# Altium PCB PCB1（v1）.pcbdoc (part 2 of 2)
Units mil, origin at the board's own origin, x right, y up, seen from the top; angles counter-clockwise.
Board outline 4301.67 x 3812.23 mil, 2 copper layers (Top Layer, Bottom Layer); 110 components, 92 nets, 368 pads, 77 vias.
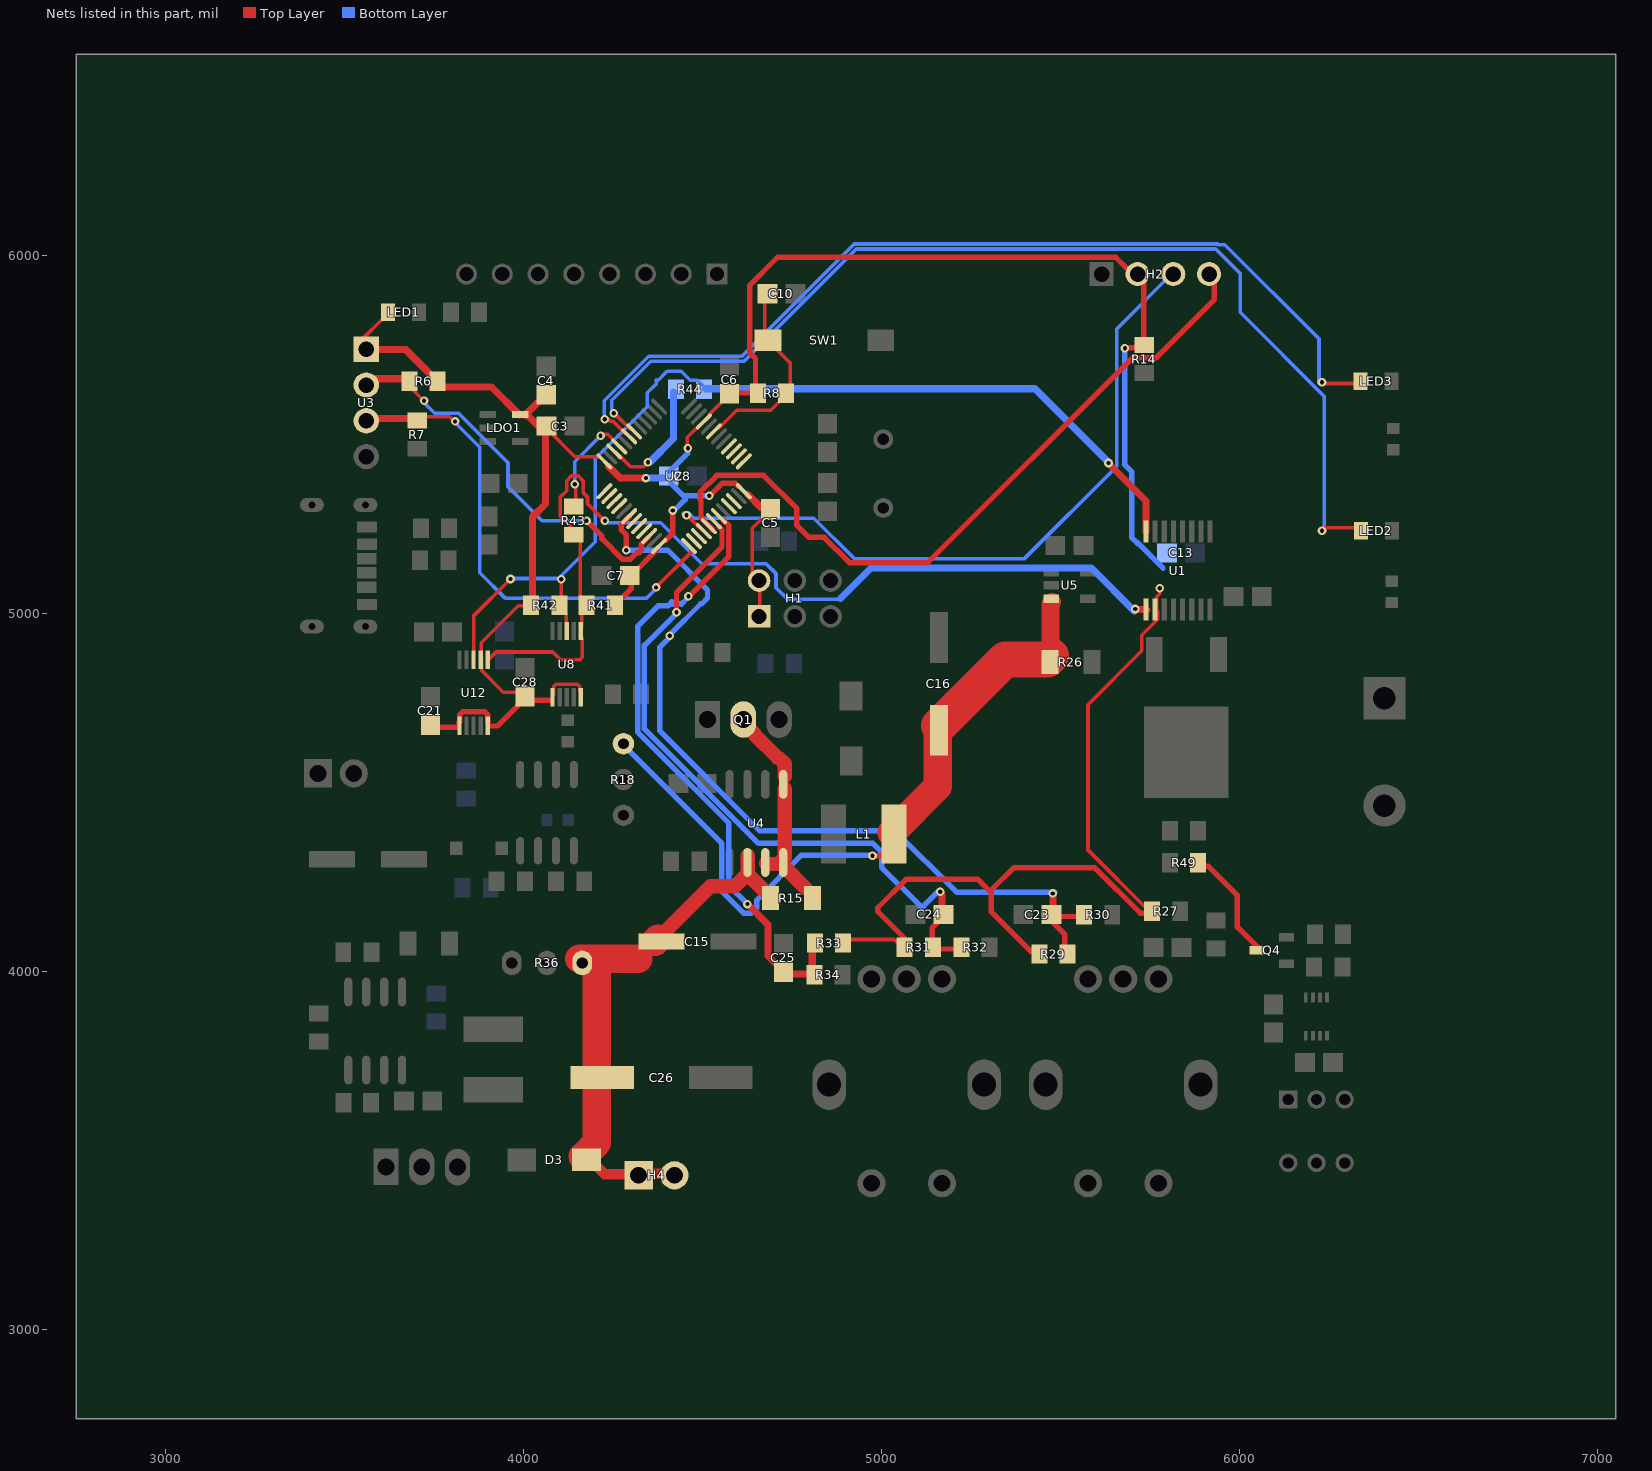
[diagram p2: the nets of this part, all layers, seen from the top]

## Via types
v1: diameter 24.02, hole 12.01, Top Layer to Bottom Layer, 77 vias

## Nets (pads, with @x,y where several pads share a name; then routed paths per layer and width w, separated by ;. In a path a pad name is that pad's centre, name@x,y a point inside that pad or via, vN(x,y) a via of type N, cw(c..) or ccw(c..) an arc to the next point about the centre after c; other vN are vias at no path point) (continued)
PA9: C23.2 R29.2 R30.1 U2.30 | length 2386.2
  Top Layer w15: v1(4287.02,5176.42) 4287.02,5218.92 4273.09,5232.85 4273.09,5248.42 U2.30@4295.09,5270.42 ; C23.2@5466.9,4149.18 5511.87,4104.22 R29.2@5511.87,4033.02 ; C23.2@5473.65,4152.93 5556.09,4152.93 R30.1@5556.84,4153.68
  Top Layer w20: C23.2@5469.03,4168.23 5479.15,4178.34 v1@5479.15,4219.94
  Bottom Layer w15: v1(4287.02,5176.42) 4402.71,5176.42 4513.91,5065.23 4513.91,5042.73 4498,5026.82 4495,5026.82 v1@4411.06,4942.88 ; v1@4408.63,4933.84 4380.91,4906.12 4380.91,4671.33 4659.86,4392.38 5038.35,4392.38 5209.67,4221.06 v1@5483.86,4221.06
  other v1: 5478.73,4217.34 4408.63,4937.59
PA10: U2.31
PA11: U2.32
PA12: U2.33
PA15: U2.38
PB0: LED2.2 U2.18 | length 2999.8
  Top Layer w10: v1@4249.48,5556.48 4255.77,5550.19 4262.34,5550.19 4296.69,5515.84 U2.18@4304.11,5515.84 ; v1@6229.18,5229.02 6239.3,5239.14 LED2.2@6337.1,5239.14
  Bottom Layer w10: v1(4252.24,5559.17) 4246.24,5565.17 4246.24,5595.24 4355.47,5704.48 4616,5704.48 4929.64,6018.12 5933.81,6018.12 6002.1,5949.83 6002.1,5841.06 6237.33,5605.83 v1@6237.33,5228.95
  other v1: 6230.87,5230.71
PB1: LED3.2 U2.19 | length 2641.5
  Top Layer w10: v1@4224.17,5542.82 4236.08,5542.82 4242.72,5536.18 4250.46,5536.18 U2.19@4282.79,5503.85 ; v1@6230.87,5642.16 6323.61,5642.16 LED3.2@6330.36,5648.9
  Bottom Layer w10: v1(4226.5,5542.49) 4225.23,5543.76 4225.23,5594.06 4349.66,5718.49 4610.19,5718.49 4923.84,6032.14 5939.61,6032.14 5941.54,6030.21 5959.38,6030.21 6222.44,5767.15 v1@6222.44,5643.21
  other v1: 6230.87,5645.53
PB3: U2.39
PB4: H2.3 U2.40 | length 2028.5
  Top Layer w10: v1@4458.62,5272.26 4458.62,5271.76 U2.40@4490.1,5240.29
  Bottom Layer w10: v1@4446.18,5278.98 4462.36,5278.98 4475.41,5265.92 4810.78,5265.92 4923.64,5153.06 5399.81,5153.06 5657.21,5410.47 5657.21,5794.43 H2.3@5819.63,5956.85
  other v1: 4455.12,5274.26
PB5: H2.4 U2.41 | length 2094.2
  Top Layer w15: U2.41@4527.23,5233.16 4527.51,5233.45 4527.51,5235.38 4495.8,5267.09 4495.8,5315.3 4493.29,5317.81 4493.29,5338.93 4539.96,5385.6 4670.57,5385.6 4763.4,5292.76 4763.4,5246.02 4797.25,5212.18 4839.71,5212.18 4910.26,5141.62 5129.25,5141.62 5701.71,5714.09 5767.1,5714.09 5930.3,5877.28 H2.4@5930.3,5961.91
PB6: C24.1 R31.2 R32.1 U2.42 | length 1965.8
  Top Layer w15: v1(4427.14,5003.13) 4427.14,5057.84 4554.53,5185.24 4554.53,5233.69 U2.42@4546.53,5241.69 ; R31.2@5141.34,4057.66 5141.34,4120.61 C24.1@5171.31,4150.59 ; R31.2@5159.32,4062.16 5217.78,4062.16 R32.1@5220.03,4064.4
  Top Layer w20: v1@5162.13,4222.19 5168.88,4215.44 C24.1@5168.88,4158.11
  Bottom Layer w15: v1(4427.14,5003.13) 4427.14,4999.91 4337.6,4910.37 4337.6,4676.85 4656.95,4357.5 4976.2,4357.5 5000.43,4333.26 5000.43,4290.23 5108.74,4181.93 5117.73,4181.93 v1@5162.7,4226.89
  other v1: 5163.96,4221.72
PB7: C25.2 R33.2 R34.1 U2.43 | length 1723.4
  Top Layer w15: v1(4460.53,5047.69) 4461.86,5047.69 4573.55,5159.38 4573.55,5245.02 U2.43@4560.21,5258.36
  Top Layer w20: v1(4625.46,4187.69) 4683.08,4130.07 4683.08,4042.51 C25.2@4726.3,3999.28 ; C25.2@4725.3,3998.29 C25.2@4729.38,3998.29 ; C25.2@4731.51,3992.08 R34.1@4801.95,3992.08 ; R34.1@4806.45,4006.32 R33.2@4806.45,4077.52
  Bottom Layer w15: 4412.62,5029.98 4403.71,5021.08 4375.97,5021.08 4318.58,4963.7 4318.58,4668.97 4573.21,4414.35 4573.21,4365.38 ; 4413.47,5032.84 4413.47,5024.66 cw(c4427.14,5003.13) 4440.12,5025.07 v1@4457.25,5042.2 ; 4573,4363.97 4573,4240.15 v1(4625.46,4187.69)
PB8: U2.45
PB9: U2.46
PB10: R43.2 U2.21 | length 277.6
  Top Layer w10: v1@4140.86,5363.29 4145.36,5358.79 R43.2@4145.36,5309.33 ; v1@4217.31,5500.44 4235.29,5500.44 U2.21@4264.52,5471.21
  Bottom Layer w10: v1@4143.11,5363.29 4143.11,5424 v1(4215.06,5495.94)
  other v1: 4143.11,5361.04
PB11: R44.2 U2.22 | length 323.5
  Top Layer w10: U2.22@4266.16,5436.97 4271.49,5436.97 4298.48,5409.98 4335.44,5409.98 v1@4345.44,5419.98
  Bottom Layer w20: v1(4347.41,5422.07) 4352.43,5422.07 4418.56,5488.2 R44.2@4418.56,5618.6
PB12: U2.25
PB13: U2.26
PB14: U2.27
PB15: U2.28
PC13: U2.2
PC14: U2.3
PC15: U2.4
PMOS-G: Q4.3 R49.1 | length 315.7
  Top Layer w15: R49.1@5885.89,4293.5 5912.87,4293.5 5994.56,4211.81 5994.56,4123.38 Q4.3@6054.52,4063.42
RESET: C10.1 R8.1 SW1.1 U2.7 | length 539
  Top Layer w10: U2.7@4544.19,5517.37 4545.58,5517.37 4595.91,5567.71 4690.64,5567.71 R8.1@4736.42,5613.49 ; C10.1@4667.29,5891.72 4674.03,5884.98 4674.03,5770.31 4744.86,5699.49 R8.1@4744.86,5616.86
SCL2: R41.2 R43.1 U1.9 U8.6 U12.6 | length 2681.9
  Top Layer w10: U12.6@3903.34,4872.32 3923.02,4892 4081.46,4892 4103.6,4869.86 4156.75,4869.86 4163.82,4876.93 4163.82,4932.17 U8.6@4157.73,4938.25 ; R43.1@4143.03,5212.79 R43.1@4145.09,5214.85 ; U8.6@4162.73,4961.35 4162.73,4995.99 R41.2@4172.72,5005.99 ; R41.2@4174.39,5026.67 4158.4,5042.66 4158.4,5201.54 R43.1@4145.09,5214.85 ; v1@4223.97,5260.76 4178.58,5306.14 4178.58,5325.2 4166.1,5337.68 4166.1,5370.57 4152.64,5384.03 4133.59,5384.03 4120.12,5370.57 4120.12,5342.91 4102.4,5325.2 4102.4,5271.51 4151.19,5222.73 4151.19,5220.96 R43.1@4145.09,5214.85
  Top Layer w20: v1@5712.15,5011.21 5739.13,5011.21 U1.9@5741.13,5009.22
  Bottom Layer w10: v1(4227.15,5258.83) 4233.09,5252.9 4383.56,5252.9 4497.47,5138.99 4677.53,5138.99 4705.34,5111.18 4705.34,5071.84 4737.23,5039.95 4886.92,5039.95
  Bottom Layer w20: 4885.76,5041.11 4971.02,5126.37 5586.51,5126.37 v1@5706.23,5006.65
  other v1: 5709.11,5012.2
SDA2: R42.2 R44.1 U1.8 U8.8 U12.8 | length 2796.5
  Top Layer w10: U12.8@3861.21,4881.72 3861.21,4994.14 v1@3962.39,5095.32 ; R42.2@4097.3,5024.77 4105.55,5033.02 v1@4105.55,5099.72 ; R42.2@4107.89,5006.86 4119,4995.76 U8.8@4119,4960.23
  Top Layer w20: v1@5635.53,5416.99 5738.96,5313.57 U1.8@5738.96,5228.13
  Bottom Layer w10: v1@3961.64,5097.4 v1@4101.13,5097.4 ; v1@4101.13,5090.96 v1@4101.13,5097.4 ; v1@4103.86,5097.4 v1@4101.13,5097.4 ; 4371.22,5653.02 4371.22,5641.94 4345.29,5616.01 4345.29,5576.98 4199.87,5431.55 4199.87,5199.69 4101.13,5100.95 v1@4101.13,5097.4 ; 4373.31,5648.43 4400.91,5676.03 4440.61,5676.03 4465.62,5651.02 4485.64,5651.02 R44.1@4501.62,5635.04
  Bottom Layer w20: R44.1@4508.64,5627.4 5429.34,5627.4 v1@5631.69,5425.05
  other v1: 4105.55,5095.22 3963.3,5096.07 5634.22,5419.99
STEP-DOWN1: Q1.2 R15.2 U4.1 U4.7 U4.8 | length 531.3
  Top Layer w40: Q1.2@4619.48,4688.94 4646.1,4662.31 4646.1,4660.06 4710.53,4595.64 4713.41,4595.64 4729.55,4579.49 U4.1@4729.55,4545.04 ; U4.7@4677.24,4301.82 4679.24,4299.82 U4.8@4719.42,4299.82 ; U4.8@4719.42,4307.88 4729.91,4318.37 U4.1@4729.91,4510.23 ; U4.8@4723.21,4299.82 U4.8@4728.2,4294.83 ; U4.8@4729.7,4290.33 R15.2@4788.66,4231.37
SWCLK: R7.2 U2.37 U3.3 | length 1368.5
  Top Layer w10: R7.2@3714.34,5548.87 3793.78,5548.87 v1@3808.77,5533.88 ; v1(4370.15,5072.5) 4469.08,5171.43 U2.37@4469.08,5178.93
  Top Layer w20: U3.3@3567.53,5544.02 3692.68,5544.02 R7.2@3700.18,5536.53
  Bottom Layer w10: v1@3808.94,5532.39 3877.51,5463.81 3877.51,5113.63 3949.54,5041.61 4343.09,5041.61 4370.15,5068.67 v1(4370.15,5072.5)
  other v1: 3808.47,5536.2
SWDIO: R6.2 U2.34 U3.2 | length 1059.9
  Top Layer w10: R6.2@3678.37,5637.31 3714.34,5601.33 v1@3714.34,5595.34
  Top Layer w15: v1(4175.95,5259) 4218.63,5216.32 4218.63,5208.76 4276.46,5150.93 4297.58,5150.93 4316.45,5169.8 4322.78,5169.8 4328.77,5175.8 4328.77,5192.75 U2.34@4347.42,5211.4
  Top Layer w20: U3.2@3568.65,5642.2 3582.14,5655.69 R6.2@3679.94,5655.69
  Bottom Layer w10: v1@3721.3,5589.25 3751.35,5559.19 3817.99,5559.19 3956.48,5420.7 3956.48,5354.07 4051.54,5259 v1(4175.95,5259)
  other v1: 3721.84,5593.84
VBAT: U2.1
VCC: C3.2 C4.2 C5.2 C6.2 C7.2 C8.2 C13.2 C21.2 C28.2 H1.1 H1.2 H2.2 LDO1.5 LED1.2 R6.1 R8.2 R14.1 R27.1 R29.1 R31.1 R33.1 R41.1 R42.1 U1.10 U2.9 U2.24 U2.36 U2.48 U3.1 U8.1 U8.5 U12.1 U12.5 U12.7 | length 8602.1
  Top Layer w10: U3.1@3535.81,5752.82 3621.81,5838.82 LED1.2@3624.34,5838.82 ; U12.7@3880.84,4877.65 3882.84,4875.64 3882.84,4840.41 3943.53,4779.72 C28.2@3999.25,4779.72 ; U12.7@3881.21,4877.65 3881.21,4918.12 3984.63,5021.54 R42.1@4013.86,5021.54 ; C3.2@4061.5,5519.1 4143.11,5437.49 U2.24@4213.93,5437.49 ; U8.1@4080.84,4771.63 4083.79,4774.59 4083.79,4795.65 4090.23,4802.08 4150.51,4802.08 4156.94,4795.65 4156.94,4781.46 U8.5@4162.28,4776.13 ; v1@4457.63,5462.44 4457.63,5491.67 U2.9@4492.85,5526.9 ; U2.9@4518.38,5550.96 4518.38,5555.43 4559.88,5596.93 C6.2@4561.02,5596.93 ; H1.2@4648.79,5104.61 4638.79,5114.61 4638.79,5238.18 C5.2@4681.04,5280.43 ; H1.1@4654.17,4990.67 4660.17,4996.67 H1.2@4660.17,5079.11 ; R33.1@4894.09,4088.69 5035.74,4088.69 R31.1@5057.09,4067.33 ; R27.1@5748.32,4167.52 5577.02,4338.82 5577.02,4744.86 5727.53,4895.36 5727.53,4938.82 5771.95,4983.24 5771.95,5006.23 ; U1.10@5769.45,5006.23 5769.45,5046.5 5777.59,5054.63 v1(5777.59,5070.05)
  Top Layer w15: C21.2@3744.46,4681.73 U12.1@3817.41,4681.73 ; U12.1@3818.9,4694.72 3821.29,4697.11 3821.29,4716.69 3829.19,4724.58 3891.54,4724.58 3899.44,4716.69 3899.44,4699.62 U12.5@3900.84,4698.22 ; U12.5@3905.31,4685.14 3927.04,4685.14 C28.2@4002.74,4760.84 ; C28.2@4006.49,4747.35 4016.23,4757.09 4073.94,4757.09 U8.1@4079.18,4751.84 ; R41.1@4245.07,5012.5 4300.53,5067.96 C7.2@4300.53,5103.93 ; C7.2@4305.77,5110.68 4371.72,5176.63 U2.36@4371.72,5178.13 ; U2.36@4396.87,5203.96 4416.85,5223.95 v1(4416.85,5287.4) ; v1@4516.28,5325.37 4554.18,5363.27 4591.98,5363.27 4600.9,5354.35 U2.48@4602.22,5354.35 ; C6.2@4576.32,5615.68 4644.94,5615.68 R8.2@4646.27,5614.34 ; R8.2@4647.9,5626.98 4647.9,5712.02 4632,5727.92 4632,5917.43 4709.55,5994.98 5654.42,5994.98 5686.85,5962.54 H2.2@5706.87,5962.54 ; R31.1@5070.51,4064.45 5070.51,4086.37 4989.57,4167.31 4989.57,4177.31 5068.95,4256.68 5269.49,4256.68 5306.59,4219.59 ; R29.1@5433.06,4054.33 5418.57,4054.33 5306.59,4166.31 5306.59,4219.59 ; v1@5677.36,5742.63 5717.83,5742.63 R14.1@5729.07,5753.87 ; H2.2@5709.75,5962.19 5732.51,5939.43 R14.1@5732.51,5762.37 ; R27.1@5761.88,4162.25 5723.1,4162.25 5596.63,4288.72 5368.98,4288.72 5306.59,4226.33 5306.59,4219.59 ; U1.10@5764.55,4996.44 U1.10@5769.45,5001.34
  Top Layer w20: U3.1@3561.1,5736.8 3670.71,5736.8 R6.1@3744.9,5662.6 ; R6.1@3761.77,5632.25 3910.16,5632.25 LDO1.5@3987.73,5554.68 ; LDO1.5@4004.22,5553.62 4048.69,5598.09 C4.2@4059.18,5598.09 ; LDO1.5@4007.72,5556.12 4042.69,5521.14 C3.2@4055.68,5521.14 ; R42.1@4024.4,5034.05 4024.4,5268.44 4061.5,5305.54 4061.5,5519.1 C3.2@4061.5,5533.18 ; U2.24@4238.03,5409.97 4270.04,5377.96 v1(4341.84,5377.96) ; U2.48@4626.97,5331.82 4662.53,5296.26 C5.2@4667.29,5296.26
  Bottom Layer w15: C8.2@4408.16,5396.49 4458.38,5446.7 v1@4458.38,5466.94 ; C8.2@4412.36,5362.85 4446.83,5328.37 ; v1(4416.85,5287.4) 4420.85,5287.4 4451.33,5317.88 ; 4451.33,5328.37 v1(4518.78,5328.37) ; v1(5680.21,5740.8) 5680.21,5414.86 5698.83,5396.24 5698.83,5212.05 5714.74,5196.14 ; 5716.98,5196.14 5786.68,5126.44
  Bottom Layer w20: v1(4341.84,5377.96) 4392,5377.96 C8.2@4392.08,5378.05
  other v1: 4459.12,5461.69
VIN: C15.2 C26.1 D3.1 H4.1 H4.2 R15.1 R36.1 U4.6 | length 1402.1
  Top Layer w30: D3.1@4189.12,3470.46 4226.59,3432.99 H4.1@4300.53,3432.99 ; H4.1@4317.02,3433.99 4417.45,3433.99 H4.2@4424.44,3426.99
  Top Layer w40: C15.2@4375.52,4090.82 4522.27,4237.64 4590.92,4237.64 4626.04,4272.76 U4.6@4626.04,4322.31 ; U4.6@4625.28,4271.34 4626.28,4271.34 4637.81,4259.82 4637.81,4259.64 4659.81,4237.64 4659.98,4237.64 R15.1@4685.74,4211.89
  Top Layer w80: R36.1@4156.3,4035.18 4319.87,4035.18 ; D3.1@4166.05,3482.27 4204.83,3521.05 4204.83,3996.11 ; C15.2@4367.93,4083.23 C15.2@4375.52,4090.82
VOUT: C16.1 L1.1 R18.3 R26.1 U5.3 | length 1953.1
  Top Layer w15: v1(4974.94,4322.71) 4996.86,4322.71 L1.1@5001.92,4327.76
  Top Layer w50: R26.1@5472.36,4879.5 5472.36,5027.61 U5.3@5476.11,5031.36
  Top Layer w80: L1.1@5028.17,4386.97 5157.45,4516.25 C16.1@5157.45,4683.75
  Top Layer w100: C16.1@5160.59,4685.77 5346.08,4871.25 R26.1@5464.11,4871.25 ; R26.1@5472.36,4879.5 R26.1@5474.23,4881.37
  Bottom Layer w15: R18.3@4283.15,4627.92 4553.98,4357.09 4553.98,4223.11 4614.9,4162.2 4636.02,4162.2 4650.95,4177.13 4650.95,4198.25 4777.1,4324.39 v1@4969.46,4324.39
pads on no net: LDO1.4 R18.2 R36.2 SW2.D SW2.E SW2.EH SW3.D SW3.E SW3.EH SW4.4 SW4.5 SW4.6 U1.13 U8.3 U8.9 U12.3 U12.9
copper on no net:
  other v1: 3742.72,3995.16 3780.44,3996.66

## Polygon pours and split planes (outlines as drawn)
GND on Top Layer (solid, remove dead copper, pour order 0): 3303.53,4679.09 3303.53,4593.09 3303.32,4593.09 3303.32,4679.09
GND on Bottom Layer (solid, remove dead copper, pour order 6): 3000,6312.23 3000,3000 6642.32,3000 6642.32,3091.06 6801.67,3091.06 6801.67,6312.23
GND on Top Layer (solid, remove dead copper, pour order 2): 3305.63,6054.66 3305.63,4707.18 3535.91,4707.18 3535.91,4679.35 3654.8,4679.35 3654.8,4611.06 3874.85,4611.06 3874.85,4583.24 4097.44,4583.24 4097.44,4651.53 4163.2,4651.53 4163.2,4747.65 4196.93,4747.65 4196.93,4839.74 4283.86,4839.74 4283.86,4898.94 4375.57,4898.94 4375.57,4965.33 4549.25,4965.33 4549.25,4963.65 4611.64,4963.65 4611.64,4913.06 4758.35,4913.06 4758.35,4906.31 4952.27,4906.31 4952.27,4951.84 4967.44,4951.84 4967.44,5009.18 5082.11,5009.18 5082.11,5078.31 5235.56,5078.31 5235.56,5074.94 5327.95,5074.94 5327.95,5177.1 5387.53,5177.1 5387.53,5263.66 5634.85,5263.66 5634.85,5232.18 5665.2,5232.18 5665.2,5214.2 5747.27,5214.2 5747.27,5204.08 5788.86,5204.08 5788.86,5197.33 5834.95,5197.33 5834.95,5201.83 5842.82,5201.83 5842.82,5267.03 5845.07,5267.03 5845.07,5290.64 5963.04,5290.64 5963.04,5260.15 6012.5,5260.15 6012.5,5206.75 6111.15,5206.75 6111.15,5148.57 6197.15,5148.57 6197.15,5006.93 6250.26,5006.93 6250.26,4966.46 6343.85,4966.46 6343.85,4943.69 6488.02,4943.69 6488.02,4933.58 6498.14,4933.58 6498.14,6043.98 6505.1,6043.98 6505.1,6054.66
GND on Top Layer (solid, remove dead copper, pour order 4): 3484.8,4650.43 3314.91,4650.43 3314.91,3345.26 6502.15,3345.26 6502.15,4883.34 6140.44,4883.34 6140.44,5109.3 5975.19,5109.3 5975.19,5188.55 5612.65,5188.55 5612.65,5298.16 5372.57,5298.16 5372.57,5254.32 5321.98,5254.32 5321.98,5160.73 5235.98,5160.73 5235.98,5031.73 5110.91,5031.73 5110.91,4956.69 5072.13,4956.69 5072.13,4926.34 4981.07,4926.34 4981.07,4902.73 4965.9,4902.73 4965.9,4862.26 4606.44,4862.26 4606.44,4876.24 4428.82,4876.24 4428.82,4863.88 4358,4863.88 4358,4834.65 4273.69,4834.65 4273.69,4722.23 4238.84,4722.23 4238.84,4694.13 4271.44,4694.13 4271.44,4659.28 4112.93,4659.28 4112.93,4655.91 4012.88,4655.91 4012.88,4577.28 3609.86,4577.28 3609.86,4608.76 3484.8,4608.76

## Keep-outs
Top Layer:
  region: 4958.52,5601.99 4982.13,5610.42 5039.46,5610.42 5039.46,5600.3 5093.42,5556.46 5086.67,5220.9 5093.42,5220.9 5093.42,5205.72 5079.93,5205.72 5079.93,5188.86 5052.95,5188.86 5052.95,5171.99 5029.34,5171.99 5029.34,5170.31 4965.26,5170.31 4965.26,5178.74 4924.79,5178.74 4924.79,5215.84 4911.3,5215.84 4911.3,5541.28 4909.62,5541.28 4918.05,5568.26
  region: 4603.65,5559.37 4708.95,5559.37 4709.44,5559.86 4709.44,5514.1 4704.03,5508.69 4702.55,5508.69 4676.47,5534.77 4674.01,5534.77 4665.65,5543.13 4597.74,5543.13 4596.76,5544.12 4596.76,5552.48
  region: 5733.46,5099.03 5733.46,5059.01 5735.09,5057.39 5761.58,5057.39 5763.75,5059.55 5763.75,5066.04 5771.32,5073.61 5771.32,5078.48 5785.38,5092.54 5785.38,5097.13 5779.43,5103.08 5747.25,5103.08 5745.36,5101.19 5735.63,5101.19
Board Outline Layer:
  circle w1: c3405.37,3453.03 r43
  region: 3448.37,3453.03 cw(c3405.37,3453.03) 3362.37,3453.03 cw(c3405.37,3453.03)
  circle w1: c3405.37,5953.03 r43
  region: 3448.37,5953.03 cw(c3405.37,5953.03) 3362.37,5953.03 cw(c3405.37,5953.03)
  circle w1: c6405.37,5953.03 r43.01
  region: 6448.38,5953.03 cw(c6405.37,5953.03) 6362.36,5953.03 cw(c6405.37,5953.03)
  circle w1: c6405.37,3453.03 r43
  region: 6448.37,3453.03 cw(c6405.37,3453.03) 6362.37,3453.03 cw(c6405.37,3453.03)
  lines w10: 3305.37,3353.03 6505.37,3353.03 6505.37,6053.03 3305.37,6053.03 3305.37,3353.03

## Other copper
Top Layer:
  drawing of 284 lines, arcs and shapes, not listed
Bottom Layer:
  region net $1N3483: 4757.72,4945.05 4747.72,4952.76 4747.58,4954.22 4747.18,4955.68 4746.55,4957.13 4745.72,4958.57 4743.58,4961.42 4740.99,4964.23 4735.49,4969.67 4733.06,4972.28 4731.16,4974.81 4777.77,4967.1 4774.03,4964.34 4770.41,4962.03 4767.02,4959.94 4763.99,4957.86 4762.64,4956.75 4761.42,4955.56 4760.36,4954.25 4759.45,4952.81 4758.72,4951.19 4758.18,4949.38 4757.84,4947.34
  region net $1N3468: 4756.3,5136.84 4766.3,5131.69 4766.44,5130.27 4766.86,5128.83 4767.52,5127.39 4768.39,5125.93 4770.63,5123.03 4773.33,5120.15 4779.08,5114.62 4781.63,5112.04 4783.61,5109.64 4736.65,5114.79 4740.32,5117.76 4743.87,5120.14 4747.18,5122.2 4750.16,5124.19 4751.48,5125.24 4752.67,5126.38 4753.72,5127.64 4754.61,5129.05 4755.33,5130.64 4755.86,5132.45 4756.18,5134.5
  region net $1N21716: 3935.83,3980.34 3920.15,3992.94 3923.74,3996.14 3927.22,3998.71 3930.46,4000.92 3933.37,4003.05 3934.67,4004.16 3935.83,4005.36 3936.86,4006.67 3937.73,4008.13 3938.43,4009.77 3938.95,4011.63 3939.27,4013.74 3939.38,4016.14 3969.86,3988.73 3964.7,3988.35 3959.93,3988.21 3955.48,3988.09 3951.29,3987.79 3947.3,3987.07 3945.36,3986.5 3943.44,3985.74 3941.53,3984.77 3939.64,3983.56 3937.74,3982.1
  region net VCC: 4446.8,5339.01 4419.27,5345.33 ccw(c4386.15,5312.21) 4399.29,5357.16 4433.14,5357.16 ccw(c4504.32,5396.53)
  region net VCC: 4347.62,5367.96 4347.62,5387.96 ccw(c4347.62,5425.46) 4377.62,5402.96 4377.62,5357.16 ccw(c4347.62,5320.89)
  region net VCC: 4423.22,5422.15 4448.77,5426.5 ccw(c4913.26,4962) 4433.14,5410.31 4403.23,5410.31 ccw(c4390.1,5455.27)
  region net $1N21810: 3987.61,4956.28 3987.61,4946.28 ccw(c3987.61,4927.53) 3972.61,4938.78 3972.61,4963.78 ccw(c3987.61,4975.03)
  region net BOOT1: 4625.08,5205.19 4625.08,5215.19 ccw(c4625.08,5233.94) 4640.08,5222.69 4640.08,5197.69 ccw(c4625.08,5186.44)
  region net $1N3468: 4764.4,5161.37 4744.83,5166.8 ccw(c4722.75,5144.72) 4731.51,5174.69 4756.51,5174.69 ccw(c4786.48,5183.45)
  region net $1N3483: 4747.72,4901.88 4757.72,4901.88 ccw(c4776.47,4901.88) 4765.22,4886.88 4740.22,4886.88 ccw(c4728.97,4901.88)
  region net BOOT0: 4669,4900.2 4686.97,4896.37 ccw(c4737.84,4947.24) 4698.7,4886.88 4676.89,4886.88 ccw(c4646.92,4878.12)
  region net I-FB: 4289.69,4395.46 4269.69,4394.24 4269.61,4395.94 4269.4,4397.55 4268.59,4400.51 4267.33,4403.19 4265.7,4405.68 4263.77,4408.05 4261.61,4410.38 4256.92,4415.24 4301.91,4416.46 4297.42,4411.43 4295.36,4409.11 4293.51,4406.79 4291.94,4404.36 4290.74,4401.73 4289.96,4398.8
  region net VOUT: 4312.58,4609.1 4299.35,4601.11 4297.83,4602.52 4296.37,4603.65 4294.97,4604.51 4293.6,4605.15 4292.25,4605.6 4290.92,4605.87 4288.2,4606.04 4282.17,4605.69 4278.62,4605.64 4274.54,4606 4308.87,4635.1 4308.65,4631.16 4308.27,4627.51 4307.91,4624.11 4307.74,4620.9 4307.95,4617.84 4308.25,4616.35 4308.71,4614.89 4309.35,4613.44 4310.19,4611.99 4311.26,4610.55
  region net $1N14439: 3808.84,4290.3 3828.84,4290.3 ccw(c3866.34,4290.3) 3843.84,4260.3 3807.15,4260.3 ccw(c3541.88,4290.3)
  region net I-FB: 3884.83,4195.48 3875.28,4214.22 ccw(c3832.86,4246.04) 3885.89,4246.04 3916.65,4206.09 ccw(c3916.65,4153.06)
  region net I-FB: 3960.48,4238.38 3960.48,4218.38 ccw(c3960.48,4175.64) 3930.48,4206.09 3930.48,4253.38 ccw(c3960.48,4275.88)
  region net $1N14642: 3877.46,4467.07 3866.53,4449.72 ccw(c3834.71,4407.29) 3834.71,4460.33 3866.85,4498.89 ccw(c3919.89,4498.89)
  region net DAC-IOUT: 3830.29,4613.65 3850.29,4613.65 ccw(c3887.79,4613.65) 3865.29,4583.65 3815.29,4583.65 ccw(c3792.79,4613.65)
  region net $1N21716: 3699.26,3932.36 3699.26,3952.36 ccw(c3699.26,4010.53) 3729.26,3960.7 3729.26,3917.36 ccw(c3699.26,3894.86)
  region net $1N21716: 3813.47,3952.81 3813.47,3932.81 ccw(c3813.47,3895.31) 3783.47,3917.81 3783.47,3960.7 ccw(c3813.47,4013.78)
  region net PB4: 5782.77,5912.92 5779.12,5923.41 5780.08,5924.6 5780.84,5926 5781.42,5927.6 5781.84,5929.37 5782.3,5933.28 5782.38,5937.52 5782.09,5946.1 5782.05,5949.99 5782.33,5953.33 5814.24,5914.58 5811.62,5914.76 5809.16,5915.07 5804.67,5915.96 5800.64,5916.96 5796.92,5917.76 5795.15,5917.99 5793.41,5918.06 5791.69,5917.92 5789.96,5917.55 5788.23,5916.9 5786.46,5915.94 5784.65,5914.62
  region net PB11: 4428.56,5568.84 4408.56,5568.84 ccw(c4317.72,5568.84) 4403.47,5598.84 4443.56,5598.84 ccw(c4466.06,5568.84)
  region net SDA2: 4467.21,5646.02 4467.21,5656.02 ccw(c4482.21,5692.44) 4482.21,5653.06 4482.21,5638.52 ccw(c4467.21,5627.27)
  region net SDA2: 4556.79,5637.4 4556.79,5617.4 ccw(c4556.79,5579.9) 4526.79,5602.4 4526.79,5652.4 ccw(c4556.79,5674.9)
  region net I-FB: 3494.74,4560.15 3494.74,4540.15 ccw(c3494.74,4502.65) 3464.74,4525.15 3464.74,4575.15 ccw(c3494.74,4597.65)
  region net I-FB: 3527.12,4493.82 3507.12,4506.19 3506.99,4507.77 3506.6,4509.44 3505.99,4511.17 3505.18,4512.95 3503.1,4516.63 3500.59,4520.36 3495.25,4527.58 3492.89,4530.84 3491.04,4533.75 3548.79,4521.38 3540.83,4515.59 3537.17,4512.69 3533.89,4509.65 3532.44,4508.04 3531.12,4506.35 3529.97,4504.57 3528.99,4502.69 3528.2,4500.69 3527.61,4498.55 3527.25,4496.27
  region net I-FB: 3474,4540.15 3469.68,4560.15 3472.23,4560.26 3474.55,4560.61 3476.67,4561.16 3478.61,4561.9 3480.39,4562.83 3482.04,4563.92 3483.59,4565.16 3485.07,4566.53 3487.89,4569.62 3490.72,4573.07 3493.77,4576.76 3497.23,4580.57 3501.56,4521.67 3499.41,4523.4 3497.51,4525.12 3494.27,4528.46 3491.52,4531.58 3488.94,4534.37 3487.62,4535.62 3486.22,4536.74 3484.71,4537.72 3483.04,4538.56 3481.17,4539.23 3479.07,4539.73 3476.69,4540.04
  region net DAC-VOUT1: 4041.56,4438.61 4053.48,4447.9 ccw(c4077.34,4479.72) 4077.34,4439.95 4049.51,4414.75 ccw(c4009.74,4414.75)
  region net $1N65377: 4118.45,4462.45 4133.45,4462.45 ccw(c4172.51,4462.45) 4140.58,4439.95 4108.83,4439.95 ccw(c4087.33,4462.45)
  region net $1N21716: 3711.41,3952.36 3711.41,3932.36 3708.77,3932.28 3706.26,3932.05 3701.88,3931.36 3698.66,3930.67 3697,3930.36 3697,3954.37 3698.66,3954.06 3701.88,3953.37 3706.26,3952.68 3708.77,3952.45
  region net PB6: 5152.19,4205.79 5146.71,4221.52 5148.34,4222.82 5150.2,4224.05 5151.93,4225.38 5152.63,4226.13 5153.16,4226.96 5159.15,4210.71 5157.94,4211.07 5156.94,4211 5156.1,4210.58 5155.37,4209.88 5153.95,4207.95 5153.14,4206.86
  region net PA8: 5830.28,4209.09 5815.78,4215.79 5817.62,4217.55 5819.18,4219.24 5819.75,4220.14 5820.12,4221.11 5820.25,4222.18 5820.08,4223.38 5836.1,4215.15 5835.33,4214.73 5834.55,4214.08 5833.01,4212.4 5831.56,4210.58
  region net PA9: 5464.24,4213.56 5471.51,4228.56 5473.93,4228.73 5475.72,4229.07 5477.51,4229.34 5479.92,4229.29 5472.64,4206.99 5471.61,4207.74 5470.61,4208.71 5468.61,4210.89 5467.58,4211.91 5466.52,4212.77 5465.41,4213.35
  region net PA9: 5459.1,4213.56 5467.5,4228.56 5471.73,4228.5 5473.71,4228.61 5475.9,4229.01 5467.51,4213.07 5466.89,4214.19 5466.15,4214.77 5465.29,4214.91 5464.3,4214.76 5461.94,4214.02 5460.58,4213.7
  region net PB6: 4423.8,4985.97 4410.78,4994.16 4412.55,4995.86 4414.06,4997.52 4414.64,4998.4 4415.05,4999.35 4415.26,5000.41 4415.23,5001.6 4430.15,4991.51 4428.95,4991.11 4428.01,4990.62 4427.25,4990.04 4426.61,4989.38 4425.4,4987.81
  region net PB7: 4456.25,5030.6 4443.99,5039.54 4445.73,5041.22 4447.24,5042.84 4447.83,5043.71 4448.26,5044.65 4448.51,5045.69 4448.55,5046.87 4462.83,5035.9 4461.66,5035.58 4460.69,5035.14 4459.89,5034.58 4459.18,5033.93 4457.85,5032.38
  region net I-VOUT: 4274.17,4914.17 4260.03,4928.31 4261.84,4930.24 4263.45,4932.17 4266.06,4935.76 4267.85,4938.52 4268.8,4939.92 4285.78,4922.94 4284.38,4921.98 4281.62,4920.2 4278.03,4917.59 4276.1,4915.98
  region net I-VOUT: 4188.16,4338.05 4208.16,4337.54 4207.95,4336.42 4207.41,4335.29 4205.9,4333.07 4205.21,4332 4204.76,4330.98 4204.67,4330.02 4205.1,4329.14 4187.44,4329.64 4188.24,4330.63 4188.68,4331.57 4188.84,4332.5 4188.8,4333.44 4188.43,4335.5
  region net $1N14439: 3828.84,4282.8 3808.84,4277.73 3808.94,4279.14 3809.18,4280.42 3809.67,4282.65 3809.73,4283.63 3809.53,4284.53 3808.98,4285.36 3807.96,4286.13 3824.89,4291.21 3824.54,4289.95 3824.75,4288.91 3825.35,4288 3826.19,4287.16 3827.11,4286.3 3827.97,4285.33 3828.6,4284.19
  region net DAC-IOUT: 3850.29,4607.6 3830.29,4605.24 3830.37,4606.61 3830.58,4607.84 3831.01,4609.96 3831.05,4610.92 3830.88,4611.83 3830.38,4612.73 3829.49,4613.64 3847.01,4616.01 3846.61,4615.01 3846.73,4614.02 3847.22,4613.03 3847.94,4612.02 3849.51,4609.92 3850.07,4608.79
  region net $1N14642: 4012.74,4396.92 4012.74,4416.92 4015.38,4417 4017.89,4417.23 4022.27,4417.92 4025.49,4418.61 4027.15,4418.92 4027.15,4394.91 4025.49,4395.22 4022.27,4395.91 4017.89,4396.6 4015.38,4396.83
  region net DAC-VOUT1: 4052.84,4455.73 4037.84,4455.73 4037.92,4458.1 4037.92,4460.25 4037.79,4461.25 4037.51,4462.23 4037.04,4463.19 4036.34,4464.13 4054.35,4464.13 4053.65,4463.19 4053.18,4462.23 4052.9,4461.25 4052.76,4460.25 4052.77,4458.1
  region net $1N65377: 4133.45,4456.59 4118.45,4452.6 4118.5,4455.07 4118.4,4457.33 4118.18,4458.37 4117.78,4459.33 4117.16,4460.21 4116.27,4461 4133.83,4465 4133.28,4463.82 4132.99,4462.8 4132.9,4461.87 4132.95,4460.97 4133.25,4459.06
  region net VOUT: 4957.41,4316.89 4959.94,4331.89 4962.33,4331.75 4964.36,4331.58 4965.31,4331.61 4966.28,4331.78 4967.27,4332.14 4968.34,4332.74 4965.81,4314.9 4964.96,4315.72 4964.05,4316.29 4963.08,4316.65 4962.05,4316.85 4959.83,4316.94
  region net PB11: 4355.56,5439.33 4367.5,5422.99 4366.47,5422.28 4365.27,5421.89 4362.69,5421.58 4361.47,5421.42 4360.42,5421.1 4359.61,5420.49 4359.14,5419.47 4349.04,5433.97 4350.31,5433.94 4351.29,5434.2 4352.07,5434.71 4352.71,5435.42 4353.92,5437.26 4354.64,5438.29
  region net SDA2: 5616.78,5425.82 5630.81,5440.08 5631.44,5439.14 5631.86,5437.96 5632.39,5435.3 5632.67,5434.05 5633.08,5433.01 5633.7,5432.28 5634.61,5431.99 5622.23,5419.39 5622.05,5420.65 5621.68,5421.62 5621.13,5422.39 5620.44,5423.02 5618.74,5424.21
  region net PB4: 4470.08,5278.32 4471.88,5262.39 4469.74,5264.44 4468.66,5265.3 4467.58,5265.96 4466.5,5266.37 4465.4,5266.45 4464.3,5266.13 4463.19,5265.37 4463.11,5283.23 4465.12,5281.69 4466.66,5280.84 4468.17,5279.96
  region net BOOT0: 4600.62,5049.83 4590.62,5049.83 4590.53,5050.97 4590.28,5052.1 4589.37,5054.32 4588.09,5056.39 4586.62,5058.24 4604.63,5058.24 4603.16,5056.39 4601.87,5054.32 4600.97,5052.1 4600.71,5050.97
  region net SDA2: 4087.7,5092.4 4090.96,5102.4 4093.19,5102.67 4095.32,5103.37 4097.38,5104.37 4099.37,5105.52 4096.1,5087.8 4094.44,5089.49 4092.32,5090.96 4089.99,5092 4088.82,5092.29
  region net SDA2: 4103.58,5110.47 4118.34,5111.09 4116.38,5109 4115.56,5107.92 4114.92,5106.83 4114.51,5105.72 4114.4,5104.59 4114.63,5103.44 4115.27,5102.27 4097.78,5104.38 4099.29,5105.81 4100.74,5107.37
  region net $1N21810: 4007.37,4946.28 4000.22,4956.28 4002.79,4956.46 4004.04,4956.71 4005.22,4957.08 4006.3,4957.61 4007.25,4958.3 4008.04,4959.18 4008.62,4960.26 4015.77,4944.45 4011.63,4945.71 4009.48,4946.12
  region net PB10: 4138.11,5377.39 4148.11,5377.39 4148.2,5376.25 4148.46,5375.12 4149.36,5372.9 4150.65,5370.83 4152.12,5368.98 4134.11,5368.98 4135.58,5370.83 4136.86,5372.9 4137.77,5375.12 4138.02,5376.25
  region net PB10: 4207.03,5480.85 4199.96,5487.92 4200.7,5488.79 4201.33,5489.77 4202.25,5491.98 4202.81,5494.35 4203.07,5496.7 4215.81,5483.96 4213.47,5483.69 4211.09,5483.14 4208.88,5482.21 4207.9,5481.59
  region net VCC: 4502.43,5320.87 4502.43,5335.87 4504.8,5335.8 4506.95,5335.79 4507.96,5335.93 4508.94,5336.21 4509.89,5336.68 4510.84,5337.38 4510.84,5319.37 4509.89,5320.07 4508.94,5320.54 4507.96,5320.82 4506.95,5320.95 4504.8,5320.95
  region net SDA2: 3978.6,5102.4 3980.6,5092.4 3979.47,5092.3 3978.31,5092.02 3976.03,5091.02 3973.93,5089.61 3972.19,5088 3970.2,5105.9 3972.13,5104.61 3974.19,5103.49 3976.35,5102.7 3977.47,5102.48
  region net SWDIO: 3736.03,5581.59 3725.11,5578.37 3723.43,5579.76 3721.55,5580.88 3719.55,5581.82 3717.5,5582.64 3733.49,5590.94 3733.32,5589.83 3733.32,5588.61 3733.76,5585.99 3734.7,5583.5 3735.32,5582.45
  region net SWDIO: 4159.6,5254 4159.6,5264 4160.74,5264.09 4161.87,5264.35 4164.09,5265.25 4166.16,5266.54 4168.01,5268.01 4168.01,5250 4166.16,5251.47 4164.09,5252.75 4161.87,5253.66 4160.74,5253.91
  region net SWCLK: 4365.63,5057.08 4355.68,5061.27 4356.4,5062.14 4357.02,5063.18 4357.94,5065.6 4358.39,5068.17 4358.31,5070.53 4373.59,5061 4371.43,5060.32 4369.33,5059.51 4367.37,5058.46
  region net +5V: 6140.92,3952.87 6132.55,3972.87 6134.02,3972.75 6135.38,3972.48 6137.77,3971.91 6138.78,3971.84 6139.65,3972.06 6140.38,3972.69 6140.96,3973.82 6149.33,3958.26 6148.49,3958.4 6147.78,3958.38 6147.19,3958.22 6146.68,3957.94 6145.86,3957.1 6145.19,3956.03 6144.5,3954.9 6143.66,3953.89 6142.52,3953.15 6141.79,3952.94
  region net +5V: 6148.78,3989.45 6168.78,3981.82 6168.71,3980.97 6168.51,3980.25 6167.8,3979.1 6166.82,3978.25 6165.75,3977.54 6164.74,3976.84 6163.96,3976.01 6163.71,3975.51 6163.59,3974.92 6163.6,3974.23 6163.78,3973.42 6147.84,3981.04 6148.96,3981.67 6149.56,3982.42 6149.78,3983.3 6149.71,3984.3 6149.16,3986.65 6148.9,3988
  region net +5V: 3747.27,4143.72 3733.13,4129.58 3731.19,4131.39 3729.26,4133 3725.68,4135.61 3722.91,4137.4 3721.52,4138.35 3738.5,4155.33 3739.45,4153.94 3741.24,4151.17 3743.85,4147.59 3745.46,4145.66
  region net +5V: 5542.32,5082.19 5528.66,5067.57 5526.89,5069.21 5525.38,5070.37 5522.79,5071.89 5520.18,5073.37 5518.64,5074.5 5516.81,5076.1 5533.3,5093.56 5534.99,5091.85 5536.22,5090.4 5537.87,5087.93 5539.49,5085.43 5540.68,5083.95
  region net PA8: 4260.99,5218.65 4250.38,5208.05 4248.76,5209.78 4247.24,5211.29 4246.43,5211.91 4245.54,5212.41 4244.54,5212.75 4243.37,5212.92 4256.11,5225.66 4256.28,5224.5 4256.63,5223.49 4257.12,5222.6 4257.74,5221.79 4259.26,5220.28
  region net PB0: 6232.33,5250.66 6242.33,5240.96 6242.37,5236.74 6242.74,5232.55 6227.56,5242.25 6228.73,5242.75 6229.73,5243.48 6230.55,5244.41 6231.21,5245.5 6231.71,5246.71 6232.06,5248
  region net PB1: 4220.23,5557.84 4230.23,5559.74 4230.33,5558.61 4230.6,5557.46 4231.6,5555.18 4233,5553.08 4234.61,5551.34 4216.7,5549.43 4218,5551.37 4219.13,5553.42 4219.92,5555.59 4220.15,5556.7
  region net SCL2: 5689.03,5009.71 5698.29,5028.73 5699.23,5027.63 5699.99,5026.51 5701.25,5024.5 5701.9,5023.75 5702.68,5023.27 5703.65,5023.15 5704.89,5023.44 5698.26,5007.06 5697.41,5008.28 5696.43,5008.83 5695.33,5008.91 5694.15,5008.74 5692.9,5008.52 5691.62,5008.47 5690.32,5008.8 5689.67,5009.17
  region net SCL2: 4247.15,5257.9 4238.01,5247.9 4233.79,5247.66 4229.61,5247.08 4238.75,5261.95 4239.23,5260.76 4239.95,5259.82 4240.86,5259.11 4241.94,5258.6 4243.14,5258.25 4244.43,5258.04
  region net VCC: 4465.88,5446.7 4450.88,5446.7 4450.94,5448.83 4450.95,5450.75 4450.61,5452.56 4450.22,5453.44 4449.64,5454.33 4467.62,5453.2 4467.06,5452.54 4466.64,5451.81 4466.12,5450.22 4465.91,5448.49
  region net SDA2: 4398.06,5666.11 ccw(c4626.24,5437.93) 4376.22,5641.94 4371.22,5651.34
  region net SCL2: 4859.48,5034.95 4857.86,5044.95 ccw(c4857.86,5133.65) 4877.86,5047.23 4879.48,5033.33 ccw(c4859.48,4910.79)

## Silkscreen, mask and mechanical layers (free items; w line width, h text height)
Top Silkscreen Layer:
  lines w10: 5240.37,4998.03 6270.37,4998.03 6270.37,6028.03 5240.37,6028.03 5240.37,4998.03
  text "CV" at 6314.86,5691.69 h120
  text "CC" at 6312.62,5269.3 h120
  text "电 / 压" at 4705.37,3383.03 h120
  text "电 / 流" at 5910.37,3383.03 h120
Mechanical Layer:
  circle w1: c3405.37,3453.03 r43
  circle w1: c3405.37,5953.03 r43
  circle w1: c6405.37,5953.03 r43.01
  circle w1: c6405.37,3453.03 r43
